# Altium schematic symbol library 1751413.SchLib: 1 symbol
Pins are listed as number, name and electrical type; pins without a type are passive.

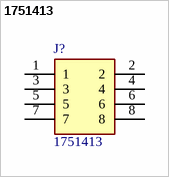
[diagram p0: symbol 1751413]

## 1751413
designator J?
PCB terminal block, 3.5mm pitch, 2 level; Manufacturer_Name: Phoenix Contact; Geometry.Height: 16.35mm
footprint 1751413
pins: 1, 2, 3, 4, 5, 6, 7, 8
